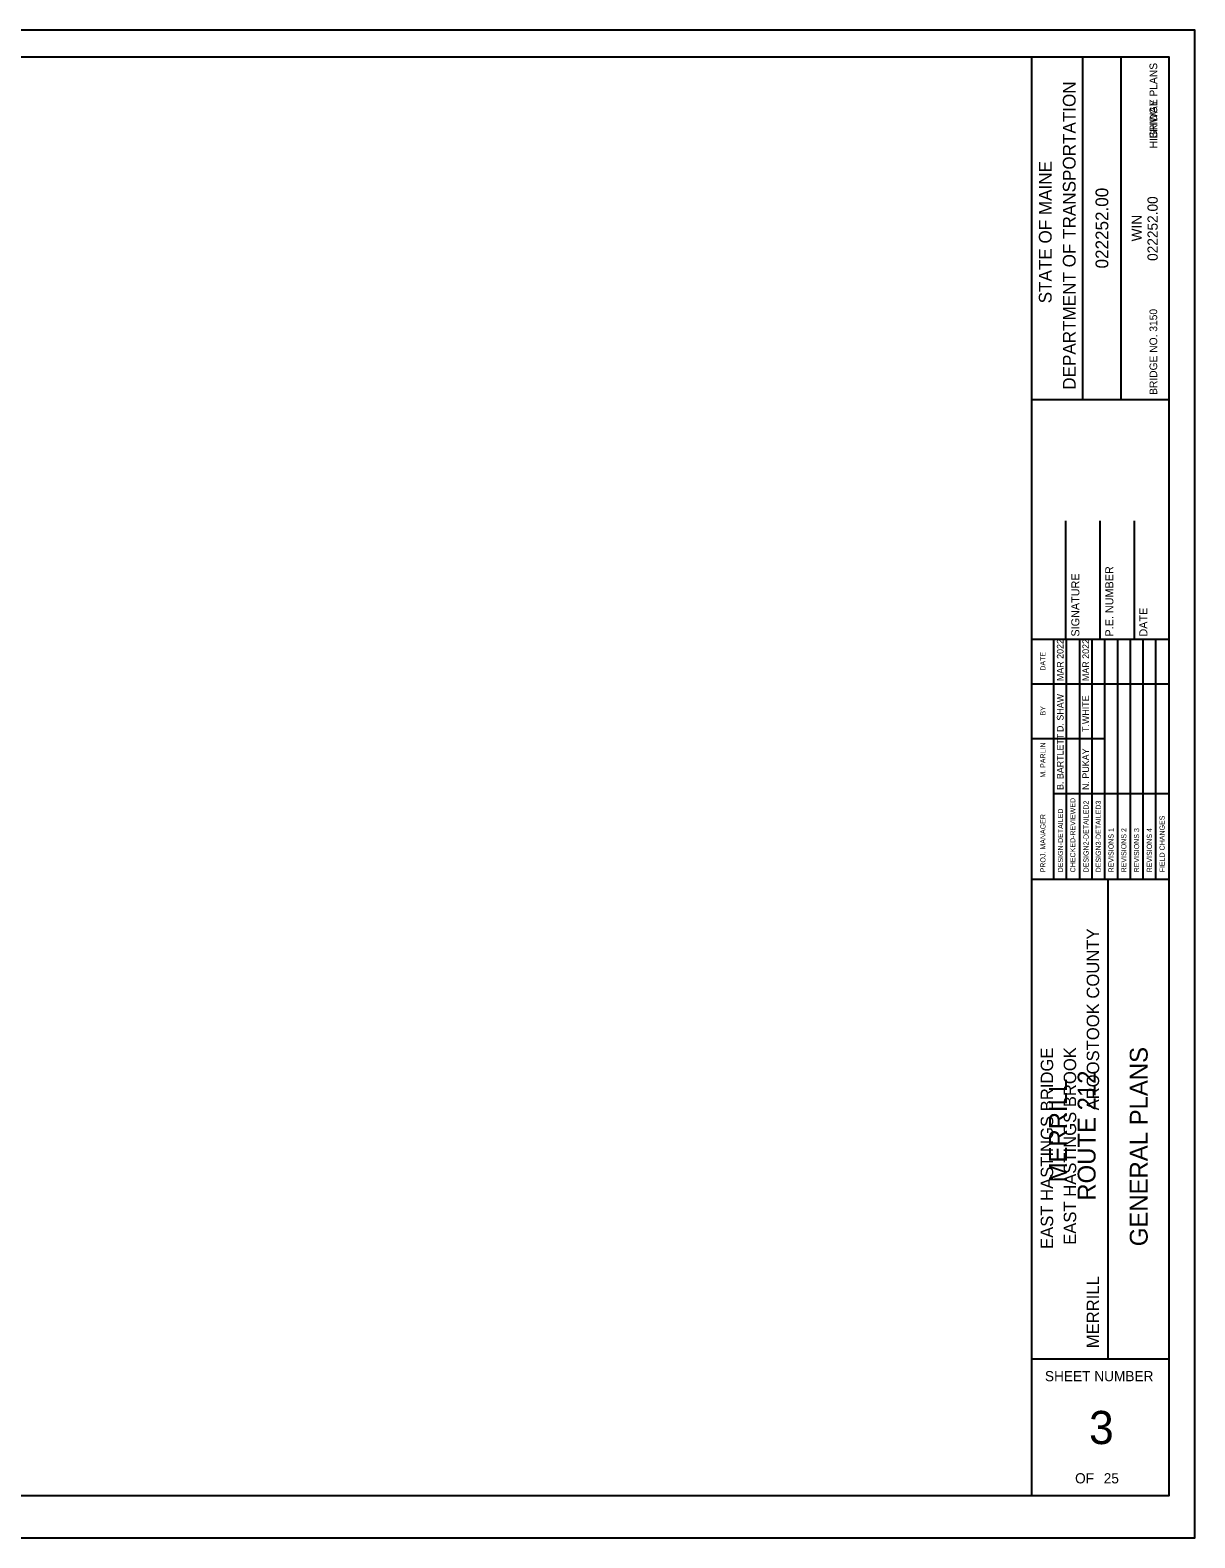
# Model space of a CAD drawing. Extents: x -414 to 436, y -253 to 297.
# Drawn here: x 11 to 436, y -253 to 297 of the extents above; entities that cross this region are included whole.
import ezdxf

# ---------------------------------------------------------------- set-up
doc = ezdxf.new("R2010")
doc.units = 0
for name, color, linetype in [('BORDER', 7, 'Continuous'), ('BRIDGE_TITLE', 7, 'Continuous'), ('HIGHWAY_TITLE', 7, 'Continuous'), ('PLOT BOUNDARY', 7, 'Continuous')]:
    doc.layers.add(name, color=color, linetype=linetype)

msp = doc.modelspace()

# ---------------------------------------------------------------- linework, layer by layer
at = {"layer": 'BORDER'}
for p, q in [((376.25, -237.74), (376.25, 287.26)), ((394.89, 162.25), (394.89, 287.25)), ((408.87, 162.25), (408.87, 287.25)), ((376.25, 162.23), (426.25, 162.23)), ((388.75, 74.78), (388.75, 118.01)), ((401.25, 74.78), (401.25, 118.01)), ((413.75, 74.78), (413.75, 118.01)), ((376.25, 74.78), (426.25, 74.78)), ((376.25, -12.72), (426.25, -12.72)), ((404.21, -187.72), (404.21, -12.72)), ((376.25, -187.72), (426.25, -187.72))]:
    msp.add_line(p, q, dxfattribs=at)
msp.add_lwpolyline([(-373.75, 287.26), (426.25, 287.26), (426.25, -237.74), (-373.75, -237.74)], close=True, dxfattribs=at)
for points in [[(384.32, 58.53), (384.32, 74.78)], [(388.99, -12.71), (388.99, 74.78)], [(393.65, 74.78), (393.65, -12.71)], [(398.3, -12.71), (398.3, 74.78)], [(402.96, -12.71), (402.96, 74.78)], [(407.62, -12.71), (407.62, 74.78)], [(412.28, -12.71), (412.28, 74.78)], [(416.94, -12.71), (416.94, 74.78)], [(421.6, -12.71), (421.6, 74.78)], [(384.33, -12.71), (384.33, 71.25)], [(376.25, 58.53), (426.25, 58.53)], [(376.25, 38.53), (384.33, 38.53)], [(384.32, 38.53), (402.96, 38.53)], [(384.32, 18.53), (426.25, 18.53)]]:
    msp.add_lwpolyline(points, dxfattribs=at)
at = {"layer": 'PLOT BOUNDARY'}
msp.add_lwpolyline([(-414.22, -253.03), (435.78, -253.03), (435.78, 296.97), (-414.22, 296.97)], close=True, dxfattribs=at)

# ---------------------------------------------------------------- texts
at = {"layer": 'BORDER'}
for s, height, p in [('DEPARTMENT OF TRANSPORTATION', 4.6588, (392.28, 165.79)), ('STATE OF MAINE', 4.6588, (383.53, 197.32)), ('022252.00', 4.659, (404.21, 210.03)), ('022252.00', 3.726, (422.23, 212.79)), ('WIN', 3.726, (416.43, 219.91)), ('P.E. NUMBER', 2.9528, (406.05, 75.74)), ('SIGNATURE', 2.953, (393.65, 75.74)), ('DATE', 2.953, (418.46, 75.74)), ('MAR 2022', 2.423, (387.86, 59.52)), ('MAR 2022', 2.423, (397.18, 59.53)), ('DATE', 1.857, (381.27, 63.31)), ('BY', 1.857, (381.27, 46.95)), ('D. SHAW', 2.423, (387.86, 40.95)), ('T.WHITE', 2.423, (397.18, 40.95)), ('B. BARTLETT', 2.4227, (387.86, 19.8)), ('M. PARLIN', 1.864, (381.27, 24.26)), ('N. PUKAY', 2.423, (397.18, 19.8)), ('DESIGN-DETAILED', 1.8637, (387.68, -10.28)), ('CHECKED-REVIEWED', 1.8637, (392.16, -10.28)), ('DESIGN2-DETAILED2', 1.8637, (397, -10.28)), ('DESIGN3-DETAILED3', 1.8637, (401.47, -10.28)), ('PROJ. MANAGER', 1.8637, (381.27, -10.28)), ('FIELD CHANGES', 1.8637, (424.76, -10.28)), ('REVISIONS 1', 1.8637, (406.13, -10.28)), ('REVISIONS 2', 1.8637, (410.79, -10.28)), ('REVISIONS 3', 1.8637, (415.45, -10.28)), ('REVISIONS 4', 1.8637, (420.11, -10.28)), ('GENERAL PLANS', 6.5214, (418.57, -146.65))]:
    msp.add_text(s, height=height, rotation=90, dxfattribs=at).set_placement(p)
for s, height, p in [('SHEET NUMBER', 3.7264, (381.08, -195.91)), ('3', 12.1, (397.18, -218.83)), ('OF', 3.726, (392.08, -233.17)), ('25', 3.726, (402.53, -233.17))]:
    msp.add_text(s, height=height, dxfattribs=at).set_placement(p)
at = {"layer": 'BRIDGE_TITLE'}
for s, height, p in [('BRIDGE PLANS', 2.795, (422.04, 257.38)), ('BRIDGE NO. 3150', 2.795, (422.04, 163.91)), ('AROOSTOOK COUNTY', 4.5358, (400.85, -97.11)), ('EAST HASTINGS BRIDGE', 4.5358, (384.08, -147.64)), ('EAST HASTINGS BROOK', 4.5358, (392.47, -146.15)), ('MERRILL', 4.536, (400.85, -183.86))]:
    msp.add_text(s, height=height, rotation=90, dxfattribs=at).set_placement(p)
at = {"layer": 'HIGHWAY_TITLE'}
for s, height, p in [('HIGHWAY PLANS', 2.795, (422.04, 253.84)), ('MERRILL', 6.521, (389.11, -123.38)), ('ROUTE 212', 6.521, (399.55, -130.04))]:
    msp.add_text(s, height=height, rotation=90, dxfattribs=at).set_placement(p)

doc.saveas('drawing.dxf')
